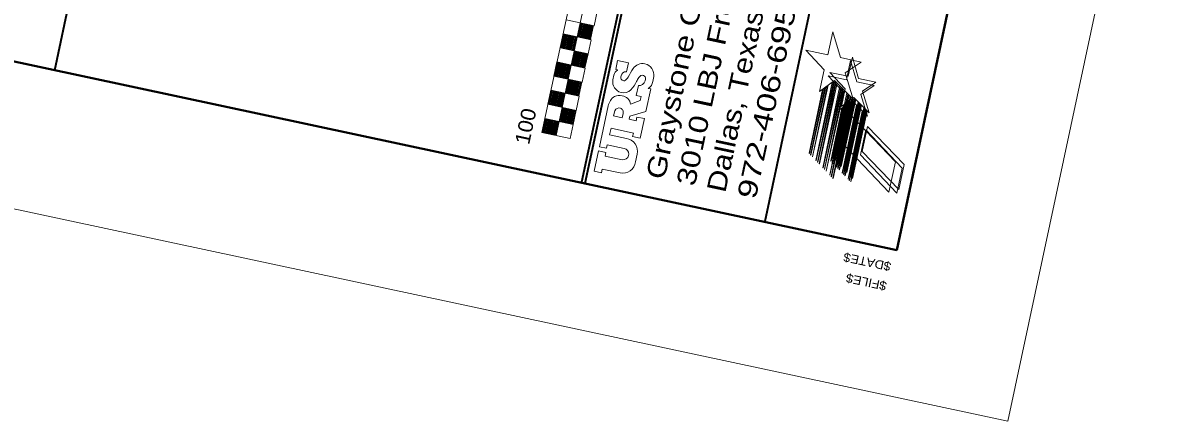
# Model space of a CAD drawing. Extents: x 2363411 to 2369126, y 6976878 to 6988319.
# Drawn here: x 2366249 to 2367036, y 6977197 to 6977474 of the extents above; entities that cross this region are included whole.
import ezdxf
from ezdxf.enums import TextEntityAlignment as Align

# ---------------------------------------------------------------- set-up
doc = ezdxf.new("R2010")
doc.units = 0
doc.header["$LTSCALE"] = 2
for name, color, linetype, lineweight in [('44', 7, 'Continuous', 40), ('62', 7, 'Continuous', 13), ('63', 7, 'Continuous', 13)]:
    doc.layers.add(name, color=color, linetype=linetype, lineweight=lineweight)
doc.layers.add('60', color=7, linetype='Continuous')

msp = doc.modelspace()

# ---------------------------------------------------------------- linework, layer by layer
at = {"layer": '44'}
msp.add_line((2366855.207, 6977316.18), (2363530.109, 6978026.648), dxfattribs=at)
at = {"layer": '44', "lineweight": 13}
msp.add_line((2363411.416, 6977949.748), (2366932.108, 6977197.487), dxfattribs=at)
at = {"layer": '62'}
for p, q in [((2369126.202, 6987466.173), (2366932.108, 6977197.487)), ((2366609.253, 6977397.699), (2366692.845, 6977788.923)), ((2366619.034, 6977395.61), (2366702.626, 6977786.834)), ((2366633.673, 6977464.071), (2366635.763, 6977473.852)), ((2366634.162, 6977463.967), (2366636.252, 6977473.748)), ((2366634.651, 6977463.862), (2366636.741, 6977473.644)), ((2366635.14, 6977463.758), (2366637.23, 6977473.54)), ((2366635.629, 6977463.653), (2366637.719, 6977473.434)), ((2366636.118, 6977463.549), (2366638.208, 6977473.331)), ((2366636.607, 6977463.445), (2366638.697, 6977473.226)), ((2366637.096, 6977463.339), (2366639.186, 6977473.122)), ((2366637.585, 6977463.235), (2366639.675, 6977473.017)), ((2366638.074, 6977463.13), (2366640.164, 6977472.912)), ((2366638.563, 6977463.027), (2366640.653, 6977472.809)), ((2366639.052, 6977462.922), (2366641.142, 6977472.703)), ((2366639.541, 6977462.817), (2366641.631, 6977472.6)), ((2366640.03, 6977462.713), (2366642.12, 6977472.495)), ((2366640.52, 6977462.609), (2366642.61, 6977472.389)), ((2366641.009, 6977462.504), (2366643.099, 6977472.286)), ((2366641.497, 6977462.4), (2366643.588, 6977472.18)), ((2366621.804, 6977456.38), (2366623.893, 6977466.162)), ((2366622.293, 6977456.275), (2366624.383, 6977466.057)), ((2366622.783, 6977456.17), (2366624.872, 6977465.951)), ((2366623.273, 6977456.067), (2366625.36, 6977465.847)), ((2366623.76, 6977455.962), (2366625.85, 6977465.742)), ((2366623.882, 6977466.164), (2366633.663, 6977464.074)), ((2366624.249, 6977455.857), (2366626.339, 6977465.639)), ((2366624.738, 6977455.754), (2366626.828, 6977465.533)), ((2366625.227, 6977455.648), (2366627.317, 6977465.429)), ((2366625.717, 6977455.545), (2366627.806, 6977465.325)), ((2366626.206, 6977455.44), (2366628.295, 6977465.22)), ((2366626.694, 6977455.335), (2366628.784, 6977465.116)), ((2366627.182, 6977455.23), (2366629.274, 6977465.012)), ((2366627.672, 6977455.126), (2366629.762, 6977464.906)), ((2366628.162, 6977455.022), (2366630.251, 6977464.802)), ((2366628.65, 6977454.917), (2366630.74, 6977464.697)), ((2366629.139, 6977454.812), (2366631.229, 6977464.594)), ((2366629.629, 6977454.709), (2366631.718, 6977464.488)), ((2366630.117, 6977454.603), (2366632.207, 6977464.384)), ((2366641.986, 6977462.295), (2366644.077, 6977472.077)), ((2366642.475, 6977462.191), (2366644.566, 6977471.972)), ((2366642.965, 6977462.085), (2366645.055, 6977471.867)), ((2366630.606, 6977454.5), (2366632.696, 6977464.28)), ((2366631.095, 6977454.395), (2366633.185, 6977464.175)), ((2366633.661, 6977464.073), (2366643.443, 6977461.984)), ((2366633.662, 6977464.074), (2366643.442, 6977461.984)), ((2366621.792, 6977456.382), (2366631.572, 6977454.293)), ((2366629.817, 6977444.441), (2366631.908, 6977454.222)), ((2366630.307, 6977444.336), (2366632.397, 6977454.117)), ((2366630.795, 6977444.231), (2366632.886, 6977454.014)), ((2366631.284, 6977444.128), (2366633.375, 6977453.908)), ((2366631.774, 6977444.022), (2366633.864, 6977453.805)), ((2366632.262, 6977443.918), (2366634.354, 6977453.699)), ((2366632.752, 6977443.813), (2366634.842, 6977453.594)), ((2366633.241, 6977443.709), (2366635.331, 6977453.49)), ((2366633.729, 6977443.604), (2366635.82, 6977453.386)), ((2366634.219, 6977443.5), (2366636.309, 6977453.281)), ((2366634.708, 6977443.396), (2366636.799, 6977453.177)), ((2366635.197, 6977443.291), (2366637.286, 6977453.073)), ((2366635.686, 6977443.187), (2366637.775, 6977452.969)), ((2366636.175, 6977443.081), (2366638.264, 6977452.864)), ((2366636.665, 6977442.976), (2366638.754, 6977452.759)), ((2366637.154, 6977442.873), (2366639.244, 6977452.654)), ((2366637.643, 6977442.768), (2366639.732, 6977452.55)), ((2366638.132, 6977442.664), (2366640.221, 6977452.446)), ((2366638.622, 6977442.559), (2366640.711, 6977452.341)), ((2366639.11, 6977442.455), (2366641.2, 6977452.237)), ((2366617.947, 6977436.749), (2366620.038, 6977446.53)), ((2366618.437, 6977436.645), (2366620.526, 6977446.425)), ((2366618.927, 6977436.54), (2366621.016, 6977446.321)), ((2366619.416, 6977436.436), (2366621.506, 6977446.216)), ((2366619.701, 6977446.603), (2366629.483, 6977444.512)), ((2366619.905, 6977436.331), (2366621.993, 6977446.112)), ((2366620.394, 6977436.228), (2366622.483, 6977446.008)), ((2366620.883, 6977436.122), (2366622.973, 6977445.904)), ((2366621.371, 6977436.018), (2366623.462, 6977445.799)), ((2366621.861, 6977435.914), (2366623.951, 6977445.695)), ((2366622.35, 6977435.81), (2366624.438, 6977445.59)), ((2366622.838, 6977435.704), (2366624.928, 6977445.486)), ((2366623.327, 6977435.6), (2366625.417, 6977445.38)), ((2366623.816, 6977435.495), (2366625.906, 6977445.277)), ((2366624.306, 6977435.392), (2366626.395, 6977445.171)), ((2366624.794, 6977435.286), (2366626.884, 6977445.067)), ((2366625.284, 6977435.183), (2366627.373, 6977444.963)), ((2366625.773, 6977435.078), (2366627.862, 6977444.859)), ((2366626.26, 6977434.973), (2366628.35, 6977444.754)), ((2366626.75, 6977434.869), (2366628.84, 6977444.649)), ((2366627.238, 6977434.764), (2366629.328, 6977444.545)), ((2366629.482, 6977444.513), (2366639.262, 6977442.422)), ((2366629.483, 6977444.512), (2366639.264, 6977442.423)), ((2366617.612, 6977436.821), (2366627.393, 6977434.731)), ((2366625.486, 6977424.912), (2366627.577, 6977434.692)), ((2366625.975, 6977424.808), (2366628.066, 6977434.587)), ((2366626.465, 6977424.703), (2366628.554, 6977434.483)), ((2366626.953, 6977424.599), (2366629.044, 6977434.378)), ((2366627.443, 6977424.494), (2366629.533, 6977434.274)), ((2366627.932, 6977424.39), (2366630.022, 6977434.169)), ((2366628.42, 6977424.285), (2366630.511, 6977434.065)), ((2366628.91, 6977424.181), (2366631, 6977433.96)), ((2366629.398, 6977424.076), (2366631.49, 6977433.857)), ((2366629.888, 6977423.972), (2366631.977, 6977433.752)), ((2366630.377, 6977423.867), (2366632.466, 6977433.647)), ((2366630.866, 6977423.764), (2366632.955, 6977433.543)), ((2366631.355, 6977423.658), (2366633.444, 6977433.438)), ((2366631.844, 6977423.554), (2366633.934, 6977433.334)), ((2366632.334, 6977423.45), (2366634.423, 6977433.23)), ((2366632.822, 6977423.345), (2366634.912, 6977433.124)), ((2366633.311, 6977423.241), (2366635.4, 6977433.02)), ((2366633.8, 6977423.136), (2366635.889, 6977432.916)), ((2366658.506, 6977434.23), (2366659.203, 6977437.491)), ((2366664.141, 6977437.028), (2366663.998, 6977436.357)), ((2366680.759, 6977433.591), (2366680.971, 6977434.774)), ((2366686.816, 6977436.43), (2366686.119, 6977433.169)), ((2366613.617, 6977417.222), (2366615.707, 6977427.003)), ((2366614.106, 6977417.118), (2366616.195, 6977426.897)), ((2366614.597, 6977417.013), (2366616.685, 6977426.794)), ((2366615.085, 6977416.908), (2366617.174, 6977426.688)), ((2366615.522, 6977427.041), (2366625.302, 6977424.952)), ((2366615.574, 6977416.803), (2366617.662, 6977426.584)), ((2366616.063, 6977416.699), (2366618.151, 6977426.479)), ((2366616.551, 6977416.594), (2366618.642, 6977426.376)), ((2366617.041, 6977416.491), (2366619.13, 6977426.271)), ((2366617.529, 6977416.386), (2366619.619, 6977426.166)), ((2366618.018, 6977416.282), (2366620.108, 6977426.062)), ((2366618.508, 6977416.177), (2366620.596, 6977425.958)), ((2366618.996, 6977416.073), (2366621.086, 6977425.853)), ((2366619.485, 6977415.967), (2366621.575, 6977425.749)), ((2366619.973, 6977415.863), (2366622.064, 6977425.643)), ((2366620.463, 6977415.759), (2366622.553, 6977425.539)), ((2366620.952, 6977415.654), (2366623.042, 6977425.434)), ((2366621.44, 6977415.549), (2366623.531, 6977425.331)), ((2366621.931, 6977415.446), (2366624.02, 6977425.225)), ((2366622.42, 6977415.341), (2366624.509, 6977425.121)), ((2366622.909, 6977415.237), (2366624.998, 6977425.017)), ((2366634.289, 6977423.031), (2366636.379, 6977432.811)), ((2366634.779, 6977422.927), (2366636.867, 6977432.707)), ((2366613.433, 6977417.26), (2366623.212, 6977415.171)), ((2366625.302, 6977424.952), (2366635.084, 6977422.861)), ((2366625.303, 6977424.949), (2366635.084, 6977422.86)), ((2366621.546, 6977405.3), (2366623.636, 6977415.079)), ((2366622.035, 6977405.195), (2366624.124, 6977414.974)), ((2366622.524, 6977405.091), (2366624.615, 6977414.87)), ((2366623.013, 6977404.986), (2366625.103, 6977414.766)), ((2366623.502, 6977404.882), (2366625.592, 6977414.662)), ((2366623.991, 6977404.778), (2366626.082, 6977414.557)), ((2366624.48, 6977404.672), (2366626.57, 6977414.452)), ((2366624.969, 6977404.568), (2366627.059, 6977414.347)), ((2366625.458, 6977404.464), (2366627.547, 6977414.243)), ((2366625.947, 6977404.358), (2366628.037, 6977414.139)), ((2366626.436, 6977404.255), (2366628.527, 6977414.034)), ((2366626.926, 6977404.15), (2366629.014, 6977413.929)), ((2366627.415, 6977404.046), (2366629.504, 6977413.825)), ((2366627.905, 6977403.941), (2366629.994, 6977413.721)), ((2366628.393, 6977403.836), (2366630.484, 6977413.617)), ((2366628.882, 6977403.732), (2366630.972, 6977413.511)), ((2366629.372, 6977403.627), (2366631.461, 6977413.407)), ((2366629.861, 6977403.523), (2366631.949, 6977413.303)), ((2366630.35, 6977403.418), (2366632.438, 6977413.199)), ((2366630.839, 6977403.313), (2366632.928, 6977413.095)), ((2366658.982, 6977409.161), (2366659.768, 6977412.842)), ((2366609.675, 6977397.609), (2366611.767, 6977407.39)), ((2366610.166, 6977397.505), (2366612.256, 6977407.286)), ((2366610.655, 6977397.4), (2366612.745, 6977407.181)), ((2366611.144, 6977397.296), (2366613.233, 6977407.076)), ((2366611.344, 6977407.48), (2366621.124, 6977405.39)), ((2366611.632, 6977397.191), (2366613.722, 6977406.971)), ((2366612.122, 6977397.087), (2366614.211, 6977406.867)), ((2366612.61, 6977396.982), (2366614.7, 6977406.762)), ((2366613.099, 6977396.877), (2366615.189, 6977406.659)), ((2366613.589, 6977396.774), (2366615.678, 6977406.553)), ((2366614.077, 6977396.668), (2366616.167, 6977406.449)), ((2366614.566, 6977396.564), (2366616.656, 6977406.344)), ((2366615.055, 6977396.459), (2366617.144, 6977406.24)), ((2366615.544, 6977396.355), (2366617.633, 6977406.137)), ((2366616.034, 6977396.251), (2366618.122, 6977406.031)), ((2366616.522, 6977396.146), (2366618.611, 6977405.928)), ((2366617.012, 6977396.042), (2366619.101, 6977405.823)), ((2366617.501, 6977395.938), (2366619.589, 6977405.719)), ((2366617.988, 6977395.833), (2366620.079, 6977405.614)), ((2366618.477, 6977395.728), (2366620.567, 6977405.509)), ((2366618.966, 6977395.624), (2366621.056, 6977405.405)), ((2366621.124, 6977405.39), (2366630.904, 6977403.3)), ((2366609.253, 6977397.699), (2366619.034, 6977395.61)), ((2366669.327, 6977381.873), (2366669.506, 6977382.715)), ((2366675.348, 6977382.744), (2366674.185, 6977377.316))]:
    msp.add_line(p, q, dxfattribs=at)
at = {"layer": '62', "lineweight": 40}
msp.add_line((2369007.509, 6987389.272), (2366855.207, 6977316.18), dxfattribs=at)
at = {"layer": '62', "lineweight": 35}
for p, q in [((2366271.525, 6977440.894), (2366407.557, 6978077.545)), ((2366772.778, 6977999.891), (2366636.741, 6977363.211)), ((2366846.367, 6977723.21), (2366763.652, 6977336.094))]:
    msp.add_line(p, q, dxfattribs=at)
at = {"layer": '62'}
for points in [[(2366645.533, 6977471.764), (2366647.623, 6977481.545), (2366628.061, 6977485.725), (2366625.972, 6977475.943)], [(2366641.354, 6977452.203), (2366643.443, 6977461.984), (2366623.882, 6977466.164), (2366621.792, 6977456.382)], [(2366792.19, 6977454.778), (2366804.944, 6977441.106), (2366801.739, 6977426.099), (2366812.124, 6977433.744), (2366825.048, 6977420.771), (2366819.465, 6977439.089), (2366830.563, 6977446.579), (2366816.249, 6977449.637), (2366810.971, 6977467.546), (2366807.55, 6977451.496)], [(2366637.174, 6977432.642), (2366639.264, 6977442.423), (2366619.701, 6977446.603), (2366617.612, 6977436.821)], [(2366799.16, 6977378.376), (2366810.433, 6977432.494), (2366811.316, 6977433.125), (2366799.321, 6977378.234)], [(2366800.23, 6977377.236), (2366811.969, 6977433.599), (2366812.123, 6977433.731), (2366812.665, 6977433.182), (2366800.403, 6977377.099)], [(2366632.994, 6977413.081), (2366635.084, 6977422.861), (2366615.522, 6977427.041), (2366613.433, 6977417.26)], [(2366794.45, 6977383.295), (2366803.698, 6977427.526), (2366804.451, 6977428.108), (2366794.615, 6977383.159)], [(2366795.536, 6977382.162), (2366805.242, 6977428.674), (2366806.03, 6977429.243), (2366795.672, 6977382.007)], [(2366796.702, 6977380.937), (2366806.947, 6977429.926), (2366807.717, 6977430.488), (2366796.859, 6977380.82)], [(2366801.406, 6977376.036), (2366813.221, 6977432.649), (2366813.851, 6977432.009), (2366801.567, 6977375.92)], [(2366803.968, 6977373.339), (2366815.823, 6977430.038), (2366816.43, 6977429.427), (2366804.113, 6977373.2)], [(2366805.035, 6977372.193), (2366816.904, 6977428.937), (2366817.498, 6977428.345), (2366805.193, 6977372.076)], [(2366806.197, 6977371.002), (2366818.071, 6977427.762), (2366818.672, 6977427.155), (2366806.365, 6977370.859)], [(2366808.771, 6977368.304), (2366820.654, 6977425.175), (2366821.225, 6977424.593), (2366808.923, 6977368.163)], [(2366809.818, 6977367.167), (2366821.74, 6977424.091), (2366822.303, 6977423.515), (2366809.988, 6977367.031)], [(2366811.005, 6977365.973), (2366822.901, 6977422.911), (2366823.475, 6977422.32), (2366811.137, 6977365.825)], [(2366819.132, 6977388.534), (2366849.825, 6977356.43), (2366854.298, 6977377.361), (2366823.596, 6977409.454)], [(2366628.813, 6977393.52), (2366630.904, 6977403.3), (2366611.344, 6977407.48), (2366609.253, 6977397.699)]]:
    msp.add_lwpolyline(points, close=True, dxfattribs=at)
for points in [[(2366661.657, 6977440.899), (2366661.707, 6977441.135), (2366660.372, 6977441.42), (2366661.721, 6977447.731), (2366669.193, 6977446.135), (2366667.844, 6977439.824)], [(2366682.996, 6977428.337), (2366684.679, 6977427.978), (2366681.308, 6977412.2), (2366670.187, 6977409.076), (2366669.715, 6977406.868), (2366674.556, 6977405.833), (2366675.118, 6977408.463), (2366680.274, 6977407.361), (2366677.375, 6977393.792), (2366672.113, 6977394.916), (2366672.63, 6977397.336), (2366657.161, 6977400.641), (2366656.195, 6977396.118), (2366667.77, 6977393.645)], [(2366670.707, 6977417.274), (2366677.462, 6977419.951), (2366678.024, 6977422.58), (2366674.657, 6977423.3), (2366676.14, 6977430.242)], [(2366666.264, 6977386.597), (2366654.584, 6977389.093), (2366654.089, 6977386.779), (2366649.143, 6977387.836), (2366655.211, 6977416.236)], [(2366665.526, 6977410.952), (2366664.875, 6977407.902), (2366658.982, 6977409.161)], [(2366663.428, 6977369.715), (2366651.115, 6977372.346), (2366650.576, 6977369.821), (2366645.42, 6977370.923), (2366648.431, 6977385.018), (2366653.588, 6977383.916), (2366653.048, 6977381.392), (2366664.94, 6977378.851)]]:
    msp.add_lwpolyline(points, dxfattribs=at)
for centre, radius, start, end in [((2366664.288, 6977436.417), 5.198, 120.41428, 168.07793), ((2366823.369, 6977351.607), 175.955, 149.05369, 151.29016), ((2366679.047, 6977437.528), 8.012, 78.41387, 145.29553), ((2366678.656, 6977437.406), 8.218, 353.17901, 75.91117), ((2366665.722, 6977432.731), 7.37, 168.2663, 257.09196), ((2366666.094, 6977435.802), 2.168, 165.16372, 258.08931), ((2366667.433, 6977436.518), 3.331, 82.91529, 171.20234), ((2366666.209, 6977435.248), 1.665, 250.24926, 277.37841), ((2366664.207, 6977438.512), 5.392, 294.26931, 333.80667), ((2366654.458, 6977442.728), 22.489, 316.96642, 334.86563), ((2366699.129, 6977419.935), 27.684, 144.92425, 151.42581), ((2366676.419, 6977434.717), 4.484, 266.43013, 345.46077), ((2366678.883, 6977434.695), 2.67, 74.36667, 154.52723), ((2366678.763, 6977435.183), 2.246, 349.50434, 68.02942), ((2366679.374, 6977434.104), 6.81, 302.13459, 352.11286), ((2366666.049, 6977431.807), 6.564, 252.50367, 317.59453), ((2366665.197, 6977414.189), 10.193, 123.35717, 168.41551), ((2366662.823, 6977415.059), 8.299, 75.90104, 112.9089), ((2366664.247, 6977416.644), 6.491, 5.5733, 84.72213), ((2366662.614, 6977411.621), 3.097, 69.91263, 156.76172), ((2366662.831, 6977411.825), 2.833, 342.05224, 72.61061), ((2366666.387, 6977384.598), 9.152, 348.31197, 81.303), ((2366665.929, 6977383.022), 3.591, 355.09044, 84.63511), ((2366665.59, 6977382.603), 3.807, 260.16836, 348.95723), ((2366665.307, 6977378.468), 8.952, 257.88198, 352.60463)]:
    msp.add_arc(centre, radius, start, end, dxfattribs=at)
at = {"layer": '63'}
msp.add_line((2369126.202, 6987466.173), (2366932.108, 6977197.487), dxfattribs=at)
at = {"layer": '63', "lineweight": 40}
msp.add_line((2369007.509, 6987389.272), (2366855.207, 6977316.18), dxfattribs=at)
at = {"layer": '63', "lineweight": 35}
msp.add_line((2366775.132, 6977999.006), (2366639.1, 6977362.355), dxfattribs=at)
at = {"layer": '63'}
for points in [[(2366792.19, 6977454.778), (2366804.944, 6977441.106), (2366801.739, 6977426.099), (2366812.124, 6977433.744), (2366825.048, 6977420.771), (2366819.465, 6977439.089), (2366830.563, 6977446.579), (2366816.249, 6977449.637), (2366810.971, 6977467.546), (2366807.55, 6977451.496)], [(2366808.918, 6977439.4), (2366819.458, 6977428.1), (2366816.809, 6977415.698), (2366825.391, 6977422.016), (2366836.072, 6977411.295), (2366831.458, 6977426.434), (2366840.631, 6977432.624), (2366828.8, 6977435.149), (2366824.439, 6977449.95), (2366821.611, 6977436.688)], [(2366807.727, 6977437.042), (2366818.268, 6977425.743), (2366815.619, 6977413.34), (2366824.201, 6977419.659), (2366834.883, 6977408.937), (2366830.268, 6977424.077), (2366839.441, 6977430.266), (2366827.611, 6977432.793), (2366823.249, 6977447.594), (2366820.421, 6977434.33)], [(2366799.16, 6977378.376), (2366810.433, 6977432.494), (2366811.316, 6977433.125), (2366799.321, 6977378.234)], [(2366800.23, 6977377.236), (2366811.969, 6977433.599), (2366812.123, 6977433.731), (2366812.665, 6977433.182), (2366800.403, 6977377.099)], [(2366794.45, 6977383.295), (2366803.698, 6977427.526), (2366804.451, 6977428.108), (2366794.615, 6977383.159)], [(2366795.536, 6977382.162), (2366805.242, 6977428.674), (2366806.03, 6977429.243), (2366795.672, 6977382.007)], [(2366796.702, 6977380.937), (2366806.947, 6977429.926), (2366807.717, 6977430.488), (2366796.859, 6977380.82)], [(2366801.406, 6977376.036), (2366813.221, 6977432.649), (2366813.851, 6977432.009), (2366801.567, 6977375.92)], [(2366803.968, 6977373.339), (2366815.823, 6977430.038), (2366816.43, 6977429.427), (2366804.113, 6977373.2)], [(2366805.035, 6977372.193), (2366816.904, 6977428.937), (2366817.498, 6977428.345), (2366805.193, 6977372.076)], [(2366806.197, 6977371.002), (2366818.071, 6977427.762), (2366818.672, 6977427.155), (2366806.365, 6977370.859)], [(2366808.771, 6977368.304), (2366820.654, 6977425.175), (2366821.225, 6977424.593), (2366808.923, 6977368.163)], [(2366809.818, 6977367.167), (2366821.74, 6977424.091), (2366822.303, 6977423.515), (2366809.988, 6977367.031)], [(2366810.785, 6977380.326), (2366818.428, 6977416.877), (2366819.05, 6977417.358), (2366810.922, 6977380.212)], [(2366811.005, 6977365.973), (2366822.901, 6977422.911), (2366823.475, 6977422.32), (2366811.137, 6977365.825)], [(2366811.683, 6977379.389), (2366819.705, 6977417.826), (2366820.355, 6977418.296), (2366811.795, 6977379.261)], [(2366812.647, 6977378.377), (2366821.114, 6977418.862), (2366821.749, 6977419.325), (2366812.777, 6977378.28)], [(2366813.488, 6977373.9), (2366822.804, 6977418.626), (2366823.534, 6977419.148), (2366813.62, 6977373.783)], [(2366814.372, 6977372.959), (2366824.073, 6977419.539), (2366824.201, 6977419.649), (2366824.649, 6977419.195), (2366814.514, 6977372.845)], [(2366814.679, 6977376.26), (2366823.994, 6977420.983), (2366824.724, 6977421.506), (2366814.811, 6977376.142)], [(2366815.344, 6977371.967), (2366825.109, 6977418.753), (2366825.63, 6977418.225), (2366815.477, 6977371.87)], [(2366815.562, 6977375.319), (2366825.263, 6977421.896), (2366825.391, 6977422.006), (2366825.839, 6977421.552), (2366815.705, 6977375.205)], [(2366816.534, 6977374.326), (2366826.299, 6977421.11), (2366826.82, 6977420.582), (2366816.667, 6977374.23)], [(2366818.651, 6977372.096), (2366828.448, 6977418.953), (2366828.95, 6977418.448), (2366818.771, 6977371.983)], [(2366819.533, 6977371.151), (2366829.342, 6977418.045), (2366829.833, 6977417.553), (2366819.664, 6977371.054)], [(2366809.594, 6977377.966), (2366817.238, 6977414.52), (2366817.86, 6977415.001), (2366809.732, 6977377.852)], [(2366810.492, 6977377.029), (2366818.514, 6977415.468), (2366819.165, 6977415.939), (2366810.604, 6977376.901)], [(2366811.456, 6977376.017), (2366819.924, 6977416.504), (2366820.559, 6977416.968), (2366811.586, 6977375.92)], [(2366817.461, 6977369.737), (2366827.259, 6977416.596), (2366827.76, 6977416.09), (2366817.581, 6977369.622)], [(2366818.343, 6977368.791), (2366828.152, 6977415.686), (2366828.644, 6977415.196), (2366818.473, 6977368.693)], [(2366819.132, 6977388.534), (2366849.825, 6977356.43), (2366854.298, 6977377.361), (2366823.596, 6977409.454)], [(2366819.303, 6977367.806), (2366829.117, 6977414.715), (2366829.613, 6977414.214), (2366819.443, 6977367.688)], [(2366820.494, 6977370.167), (2366830.307, 6977417.074), (2366830.802, 6977416.571), (2366820.633, 6977370.047)], [(2366821.43, 6977365.576), (2366831.251, 6977412.577), (2366831.723, 6977412.096), (2366821.556, 6977365.46)], [(2366822.296, 6977364.637), (2366832.149, 6977411.682), (2366832.615, 6977411.205), (2366822.437, 6977364.524)], [(2366822.621, 6977367.937), (2366832.441, 6977414.935), (2366832.913, 6977414.453), (2366822.746, 6977367.82)], [(2366823.276, 6977363.649), (2366833.108, 6977410.706), (2366833.582, 6977410.217), (2366823.386, 6977363.528)], [(2366823.486, 6977366.997), (2366833.338, 6977414.039), (2366833.804, 6977413.563), (2366823.627, 6977366.884)], [(2366824.466, 6977366.009), (2366834.298, 6977413.063), (2366834.772, 6977412.575), (2366824.576, 6977365.887)], [(2366831.183, 6977384.655), (2366856.548, 6977358.123), (2366860.244, 6977375.421), (2366834.873, 6977401.944)], [(2366829.993, 6977382.295), (2366855.359, 6977355.762), (2366859.056, 6977373.062), (2366833.683, 6977399.585)]]:
    msp.add_lwpolyline(points, close=True, dxfattribs=at)

# ---------------------------------------------------------------- texts
at = {"layer": '60', "width": 1.1}
for s, p in [('$DATE$', (2366851.653, 6977307.43)), ('$FILE$', (2366848.639, 6977293.971))]:
    msp.add_text(s, height=6, rotation=167.939, dxfattribs=at).set_placement(p)
at = {"layer": '62'}
for s, width, p in [('3010 LBJ Freeway, Suite 1300', 1.25, (2366715.218, 6977359.911)), ('Dallas, Texas 75234', 1.2, (2366736.291, 6977355.409)), ('Graystone Centre', 1.25, (2366694.145, 6977364.414)), ('972-406-6950', 1.35, (2366757.364, 6977350.906))]:
    msp.add_text(s, height=13.22, rotation=77.939, dxfattribs=dict(at, width=width)).set_placement(p)
at = {"layer": '62', "width": 1.1}
msp.add_text('100', height=10.2, rotation=77.939, dxfattribs=at).set_placement((2366602.944, 6977400.993), align=Align.CENTER)

doc.saveas('drawing.dxf')
